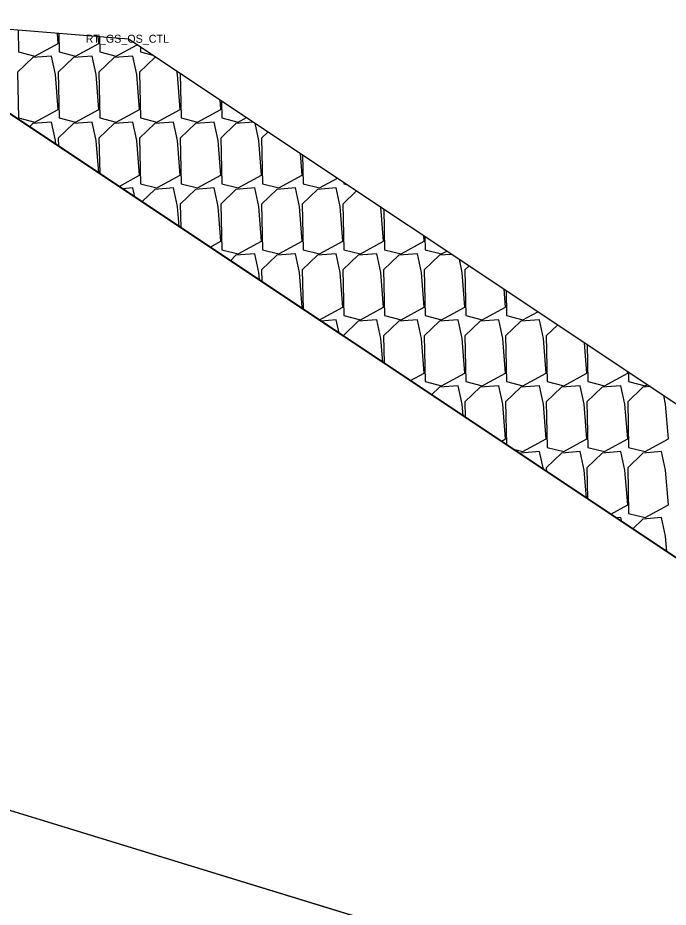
# Model space of a CAD drawing. Extents: x -26 to 2903, y -10 to 63.
# Drawn here: x 1467.77 to 1477.93, y 5.47 to 19.36 of the extents above; entities that cross this region are included whole.
import ezdxf

# ---------------------------------------------------------------- set-up
doc = ezdxf.new("R2010")
doc.units = 0
for name, color, linetype in [('Default', 7, 'Continuous'), ('Exist XS Ground Line', 7, 'Continuous'), ('Prop CMT Slope Grass', 7, 'Continuous'), ('Prop XS Earthwork Shape', 7, 'Continuous'), ('Prop XS SE Text', 7, 'Continuous'), ('Scratch_Level_0', 7, 'Continuous')]:
    doc.layers.add(name, color=color, linetype=linetype)

msp = doc.modelspace()

# ---------------------------------------------------------------- linework, layer by layer
at = {"layer": 'Default'}
msp.add_line((1465.403, 19.359), (1497.228, -1.86), dxfattribs=at)
at = {"layer": 'Exist XS Ground Line'}
msp.add_line((1464.468, 7.958), (1477.924, 3.831), dxfattribs=at)
at = {"layer": 'Prop CMT Slope Grass'}
msp.add_line((1465.4, 19.359), (1486.936, 5), dxfattribs=at)
at = {"layer": 'Prop XS Earthwork Shape'}
msp.add_lwpolyline([(1463.445, 18.658), (1449.987, 18.927), (1436.595, 19.195), (1433.224, 19.262), (1428.033, 17.55), (1428.706, 17.48), (1429.086, 17.434), (1431.817, 16.873), (1438.827, 14.563), (1445.07, 13.4), (1449.297, 12.336), (1450, 12.129), (1458.121, 9.732), (1459.835, 9.244), (1464.468, 7.958), (1474.113, 5), (1486.936, 5), (1466.544, 18.596)], close=True, dxfattribs=at)
at = {"layer": 'Prop XS SE Text'}
for p, q in [((1465.4, 19.359), (1469.5, 19.031)), ((1467.777, 19.169), (1467.784, 18.825)), ((1468.404, 18.958), (1468.391, 19.12)), ((1468.413, 19.118), (1468.419, 18.825)), ((1469.039, 18.958), (1469.03, 19.069)), ((1469.049, 19.067), (1469.054, 18.825)), ((1469.5, 19.031), (1495.585, 1.64)), ((1468.04, 18.761), (1468.404, 18.958)), ((1468.675, 18.761), (1469.039, 18.958)), ((1469.31, 18.761), (1469.638, 18.939)), ((1469.687, 18.906), (1469.689, 18.825)), ((1467.784, 18.825), (1468.04, 18.761)), ((1468.298, 18.761), (1468.005, 18.738)), ((1468.361, 18.471), (1468.298, 18.761)), ((1468.419, 18.825), (1468.675, 18.761)), ((1468.933, 18.761), (1468.64, 18.738)), ((1468.996, 18.471), (1468.933, 18.761)), ((1469.054, 18.825), (1469.31, 18.761)), ((1469.568, 18.761), (1469.275, 18.738)), ((1469.631, 18.471), (1469.568, 18.761)), ((1469.689, 18.825), (1469.881, 18.777)), ((1468.005, 18.738), (1467.769, 18.509)), ((1468.64, 18.738), (1468.404, 18.509)), ((1469.275, 18.738), (1469.039, 18.509)), ((1469.91, 18.738), (1469.674, 18.509)), ((1469.937, 18.74), (1469.91, 18.738)), ((1467.769, 18.509), (1467.784, 17.795)), ((1468.404, 18.509), (1468.419, 17.795)), ((1469.039, 18.509), (1469.054, 17.795)), ((1469.674, 18.509), (1469.689, 17.795)), ((1470.266, 18.471), (1470.253, 18.529)), ((1470.309, 18.491), (1470.324, 17.795)), ((1468.404, 17.929), (1468.361, 18.471)), ((1469.039, 17.929), (1468.996, 18.471)), ((1469.674, 17.929), (1469.631, 18.471)), ((1470.309, 17.929), (1470.266, 18.471)), ((1470.944, 17.929), (1470.932, 18.076)), ((1470.953, 18.062), (1470.959, 17.795)), ((1468.04, 17.731), (1468.404, 17.929)), ((1468.675, 17.731), (1469.039, 17.929)), ((1469.31, 17.731), (1469.674, 17.929)), ((1469.945, 17.731), (1470.309, 17.929)), ((1470.58, 17.731), (1470.944, 17.929)), ((1467.784, 17.795), (1468.04, 17.731)), ((1468.419, 17.795), (1468.675, 17.731)), ((1469.054, 17.795), (1469.31, 17.731)), ((1469.689, 17.795), (1469.945, 17.731)), ((1470.324, 17.795), (1470.58, 17.731)), ((1470.959, 17.795), (1471.215, 17.731)), ((1471.215, 17.731), (1471.344, 17.801)), ((1468.005, 17.708), (1467.953, 17.658)), ((1468.298, 17.731), (1468.005, 17.708)), ((1468.361, 17.441), (1468.298, 17.731)), ((1468.64, 17.708), (1468.404, 17.479)), ((1468.933, 17.731), (1468.64, 17.708)), ((1468.996, 17.441), (1468.933, 17.731)), ((1469.275, 17.708), (1469.039, 17.479)), ((1469.568, 17.731), (1469.275, 17.708)), ((1469.631, 17.441), (1469.568, 17.731)), ((1469.91, 17.708), (1469.674, 17.479)), ((1470.202, 17.731), (1469.91, 17.708)), ((1470.266, 17.441), (1470.202, 17.731)), ((1470.545, 17.708), (1470.309, 17.479)), ((1470.837, 17.731), (1470.545, 17.708)), ((1470.901, 17.441), (1470.837, 17.731)), ((1471.179, 17.708), (1470.944, 17.479)), ((1471.452, 17.729), (1471.179, 17.708)), ((1471.536, 17.441), (1471.476, 17.713)), ((1471.68, 17.578), (1471.579, 17.479)), ((1468.366, 17.383), (1468.361, 17.441)), ((1468.404, 17.479), (1468.406, 17.356)), ((1469.036, 16.937), (1468.996, 17.441)), ((1469.039, 17.479), (1469.051, 16.927)), ((1469.674, 16.899), (1469.631, 17.441)), ((1469.674, 17.479), (1469.689, 16.766)), ((1470.309, 16.899), (1470.266, 17.441)), ((1470.309, 17.479), (1470.324, 16.766)), ((1470.944, 16.899), (1470.901, 17.441)), ((1470.944, 17.479), (1470.959, 16.766)), ((1471.579, 16.899), (1471.536, 17.441)), ((1471.579, 17.479), (1471.594, 16.766)), ((1472.213, 16.899), (1472.187, 17.24)), ((1472.219, 17.218), (1472.229, 16.766)), ((1469.353, 16.725), (1469.674, 16.899)), ((1469.945, 16.701), (1470.309, 16.899)), ((1470.58, 16.701), (1470.944, 16.899)), ((1471.215, 16.701), (1471.579, 16.899)), ((1471.85, 16.701), (1472.213, 16.899)), ((1472.485, 16.701), (1472.765, 16.854)), ((1469.568, 16.701), (1469.407, 16.689)), ((1469.598, 16.562), (1469.568, 16.701)), ((1469.689, 16.766), (1469.945, 16.701)), ((1469.91, 16.678), (1469.711, 16.486)), ((1470.202, 16.701), (1469.91, 16.678)), ((1470.266, 16.412), (1470.202, 16.701)), ((1470.545, 16.678), (1470.309, 16.45)), ((1470.324, 16.766), (1470.58, 16.701)), ((1470.837, 16.701), (1470.545, 16.678)), ((1470.901, 16.412), (1470.837, 16.701)), ((1471.179, 16.678), (1470.944, 16.45)), ((1470.959, 16.766), (1471.215, 16.701)), ((1471.472, 16.701), (1471.179, 16.678)), ((1471.536, 16.412), (1471.472, 16.701)), ((1471.814, 16.678), (1471.579, 16.45)), ((1471.594, 16.766), (1471.85, 16.701)), ((1472.107, 16.701), (1471.814, 16.678)), ((1472.171, 16.412), (1472.107, 16.701)), ((1472.449, 16.678), (1472.213, 16.45)), ((1472.229, 16.766), (1472.485, 16.701)), ((1472.742, 16.701), (1472.449, 16.678)), ((1472.806, 16.412), (1472.742, 16.701)), ((1472.863, 16.789), (1472.864, 16.766)), ((1472.864, 16.766), (1472.918, 16.752)), ((1473.062, 16.656), (1472.848, 16.45)), ((1470.291, 16.1), (1470.266, 16.412)), ((1470.309, 16.45), (1470.317, 16.083)), ((1470.944, 15.87), (1470.901, 16.412)), ((1470.944, 16.45), (1470.959, 15.736)), ((1471.579, 15.87), (1471.536, 16.412)), ((1471.579, 16.45), (1471.594, 15.736)), ((1472.213, 15.87), (1472.171, 16.412)), ((1472.213, 16.45), (1472.229, 15.736)), ((1472.848, 15.87), (1472.806, 16.412)), ((1472.848, 16.45), (1472.864, 15.736)), ((1473.483, 15.87), (1473.441, 16.403)), ((1473.485, 16.374), (1473.499, 15.736)), ((1470.774, 15.778), (1470.944, 15.87)), ((1471.215, 15.672), (1471.579, 15.87)), ((1471.85, 15.672), (1472.213, 15.87)), ((1472.485, 15.672), (1472.848, 15.87)), ((1473.12, 15.672), (1473.483, 15.87)), ((1473.755, 15.672), (1474.118, 15.87)), ((1474.118, 15.87), (1474.111, 15.956)), ((1474.129, 15.945), (1474.134, 15.736)), ((1470.959, 15.736), (1471.215, 15.672)), ((1471.594, 15.736), (1471.85, 15.672)), ((1472.229, 15.736), (1472.485, 15.672)), ((1472.864, 15.736), (1473.12, 15.672)), ((1473.499, 15.736), (1473.755, 15.672)), ((1474.134, 15.736), (1474.389, 15.672)), ((1474.389, 15.672), (1474.471, 15.716)), ((1471.179, 15.649), (1471.093, 15.565)), ((1471.472, 15.672), (1471.179, 15.649)), ((1471.536, 15.382), (1471.472, 15.672)), ((1471.814, 15.649), (1471.579, 15.42)), ((1472.107, 15.672), (1471.814, 15.649)), ((1472.171, 15.382), (1472.107, 15.672)), ((1472.449, 15.649), (1472.213, 15.42)), ((1472.742, 15.672), (1472.449, 15.649)), ((1472.806, 15.382), (1472.742, 15.672)), ((1473.084, 15.649), (1472.848, 15.42)), ((1473.377, 15.672), (1473.084, 15.649)), ((1473.441, 15.382), (1473.377, 15.672)), ((1473.719, 15.649), (1473.483, 15.42)), ((1474.012, 15.672), (1473.719, 15.649)), ((1474.076, 15.382), (1474.012, 15.672)), ((1474.354, 15.649), (1474.118, 15.42)), ((1474.55, 15.664), (1474.354, 15.649)), ((1474.711, 15.382), (1474.666, 15.587)), ((1471.579, 15.42), (1471.582, 15.239)), ((1472.213, 15.42), (1472.227, 14.809)), ((1472.848, 15.42), (1472.864, 14.707)), ((1473.483, 15.42), (1473.499, 14.707)), ((1474.118, 15.42), (1474.134, 14.707)), ((1474.819, 15.484), (1474.753, 15.42)), ((1474.753, 15.42), (1474.769, 14.707)), ((1471.545, 15.264), (1471.536, 15.382)), ((1472.213, 14.84), (1472.171, 15.382)), ((1472.848, 14.84), (1472.806, 15.382)), ((1473.483, 14.84), (1473.441, 15.382)), ((1474.118, 14.84), (1474.076, 15.382)), ((1474.753, 14.84), (1474.711, 15.382)), ((1475.388, 14.84), (1475.366, 15.12)), ((1475.395, 15.101), (1475.403, 14.707)), ((1472.195, 14.83), (1472.213, 14.84)), ((1472.485, 14.642), (1472.848, 14.84)), ((1473.12, 14.642), (1473.483, 14.84)), ((1473.755, 14.642), (1474.118, 14.84)), ((1474.389, 14.642), (1474.753, 14.84)), ((1475.024, 14.642), (1475.388, 14.84)), ((1475.659, 14.642), (1475.892, 14.769)), ((1472.473, 14.645), (1472.485, 14.642)), ((1472.742, 14.642), (1472.505, 14.623)), ((1472.788, 14.435), (1472.742, 14.642)), ((1473.084, 14.619), (1472.851, 14.393)), ((1472.864, 14.707), (1473.12, 14.642)), ((1473.377, 14.642), (1473.084, 14.619)), ((1473.441, 14.352), (1473.377, 14.642)), ((1473.719, 14.619), (1473.483, 14.391)), ((1473.499, 14.707), (1473.755, 14.642)), ((1474.012, 14.642), (1473.719, 14.619)), ((1474.076, 14.352), (1474.012, 14.642)), ((1474.354, 14.619), (1474.118, 14.391)), ((1474.134, 14.707), (1474.389, 14.642)), ((1474.647, 14.642), (1474.354, 14.619)), ((1474.711, 14.352), (1474.647, 14.642)), ((1474.989, 14.619), (1474.753, 14.391)), ((1474.769, 14.707), (1475.024, 14.642)), ((1475.282, 14.642), (1474.989, 14.619)), ((1475.345, 14.352), (1475.282, 14.642)), ((1475.624, 14.619), (1475.388, 14.391)), ((1475.403, 14.707), (1475.659, 14.642)), ((1475.917, 14.642), (1475.624, 14.619)), ((1475.98, 14.352), (1475.917, 14.642)), ((1476.201, 14.563), (1476.023, 14.391)), ((1473.47, 13.98), (1473.441, 14.352)), ((1473.483, 14.391), (1473.492, 13.965)), ((1474.118, 13.81), (1474.076, 14.352)), ((1474.118, 14.391), (1474.134, 13.677)), ((1474.753, 13.81), (1474.711, 14.352)), ((1474.753, 14.391), (1474.769, 13.677)), ((1475.388, 13.81), (1475.345, 14.352)), ((1475.388, 14.391), (1475.403, 13.677)), ((1476.023, 13.81), (1475.98, 14.352)), ((1476.023, 14.391), (1476.038, 13.677)), ((1476.658, 13.81), (1476.621, 14.283)), ((1476.661, 14.257), (1476.673, 13.677)), ((1473.902, 13.692), (1474.118, 13.81)), ((1474.389, 13.613), (1474.753, 13.81)), ((1475.024, 13.613), (1475.388, 13.81)), ((1475.659, 13.613), (1476.023, 13.81)), ((1476.294, 13.613), (1476.658, 13.81)), ((1476.929, 13.613), (1477.293, 13.81)), ((1477.293, 13.81), (1477.291, 13.837)), ((1477.305, 13.827), (1477.308, 13.677)), ((1474.134, 13.677), (1474.389, 13.613)), ((1474.769, 13.677), (1475.024, 13.613)), ((1475.403, 13.677), (1475.659, 13.613)), ((1476.038, 13.677), (1476.294, 13.613)), ((1476.673, 13.677), (1476.929, 13.613)), ((1477.308, 13.677), (1477.564, 13.613)), ((1477.564, 13.613), (1477.599, 13.631)), ((1474.354, 13.589), (1474.233, 13.472)), ((1474.647, 13.613), (1474.354, 13.589)), ((1474.711, 13.323), (1474.647, 13.613)), ((1474.989, 13.589), (1474.753, 13.361)), ((1475.282, 13.613), (1474.989, 13.589)), ((1475.345, 13.323), (1475.282, 13.613)), ((1475.624, 13.589), (1475.388, 13.361)), ((1475.917, 13.613), (1475.624, 13.589)), ((1475.98, 13.323), (1475.917, 13.613)), ((1476.259, 13.589), (1476.023, 13.361)), ((1476.552, 13.613), (1476.259, 13.589)), ((1476.615, 13.323), (1476.552, 13.613)), ((1476.894, 13.589), (1476.658, 13.361)), ((1477.187, 13.613), (1476.894, 13.589)), ((1477.25, 13.323), (1477.187, 13.613)), ((1477.529, 13.589), (1477.293, 13.361)), ((1477.647, 13.599), (1477.529, 13.589)), ((1474.753, 13.361), (1474.758, 13.121)), ((1475.388, 13.361), (1475.403, 12.692)), ((1476.023, 13.361), (1476.038, 12.647)), ((1476.658, 13.361), (1476.673, 12.647)), ((1477.293, 13.361), (1477.308, 12.647)), ((1477.885, 13.323), (1477.855, 13.46)), ((1474.725, 13.144), (1474.711, 13.323)), ((1475.388, 12.781), (1475.345, 13.323)), ((1476.023, 12.781), (1475.98, 13.323)), ((1476.658, 12.781), (1476.615, 13.323)), ((1477.293, 12.781), (1477.25, 13.323)), ((1477.928, 12.781), (1477.885, 13.323)), ((1475.323, 12.745), (1475.388, 12.781)), ((1475.659, 12.583), (1476.023, 12.781)), ((1476.294, 12.583), (1476.658, 12.781)), ((1476.929, 12.583), (1477.293, 12.781)), ((1477.564, 12.583), (1477.928, 12.781)), ((1476.038, 12.647), (1476.294, 12.583)), ((1476.673, 12.647), (1476.929, 12.583)), ((1477.308, 12.647), (1477.564, 12.583)), ((1475.509, 12.621), (1475.659, 12.583)), ((1475.624, 12.56), (1475.614, 12.551)), ((1475.917, 12.583), (1475.624, 12.56)), ((1475.977, 12.309), (1475.917, 12.583)), ((1476.259, 12.56), (1476.023, 12.331)), ((1476.552, 12.583), (1476.259, 12.56)), ((1476.615, 12.293), (1476.552, 12.583)), ((1476.894, 12.56), (1476.658, 12.331)), ((1477.187, 12.583), (1476.894, 12.56)), ((1477.25, 12.293), (1477.187, 12.583)), ((1477.529, 12.56), (1477.293, 12.331)), ((1477.822, 12.583), (1477.529, 12.56)), ((1477.885, 12.293), (1477.822, 12.583)), ((1476.023, 12.331), (1476.024, 12.277)), ((1476.649, 11.86), (1476.615, 12.293)), ((1476.658, 12.331), (1476.668, 11.848)), ((1477.293, 11.751), (1477.25, 12.293)), ((1477.293, 12.331), (1477.308, 11.618)), ((1477.928, 11.751), (1477.885, 12.293)), ((1477.029, 11.607), (1477.293, 11.751)), ((1477.564, 11.553), (1477.928, 11.751)), ((1477.187, 11.553), (1477.118, 11.548)), ((1477.2, 11.493), (1477.187, 11.553)), ((1477.308, 11.618), (1477.564, 11.553)), ((1477.529, 11.53), (1477.372, 11.379)), ((1477.822, 11.553), (1477.529, 11.53)), ((1477.885, 11.264), (1477.822, 11.553)), ((1477.904, 11.024), (1477.885, 11.264))]:
    msp.add_line(p, q, dxfattribs=at)

# ---------------------------------------------------------------- texts
at = {"layer": 'Scratch_Level_0'}
msp.add_text('RT_GS_OS_CTL', height=0.125, dxfattribs=at).set_placement((1468.832, 18.969))
msp.add_text('RT_GS_OS_CTL', height=0.125, dxfattribs=at).set_placement((1468.832, 18.969))

doc.saveas('drawing.dxf')
